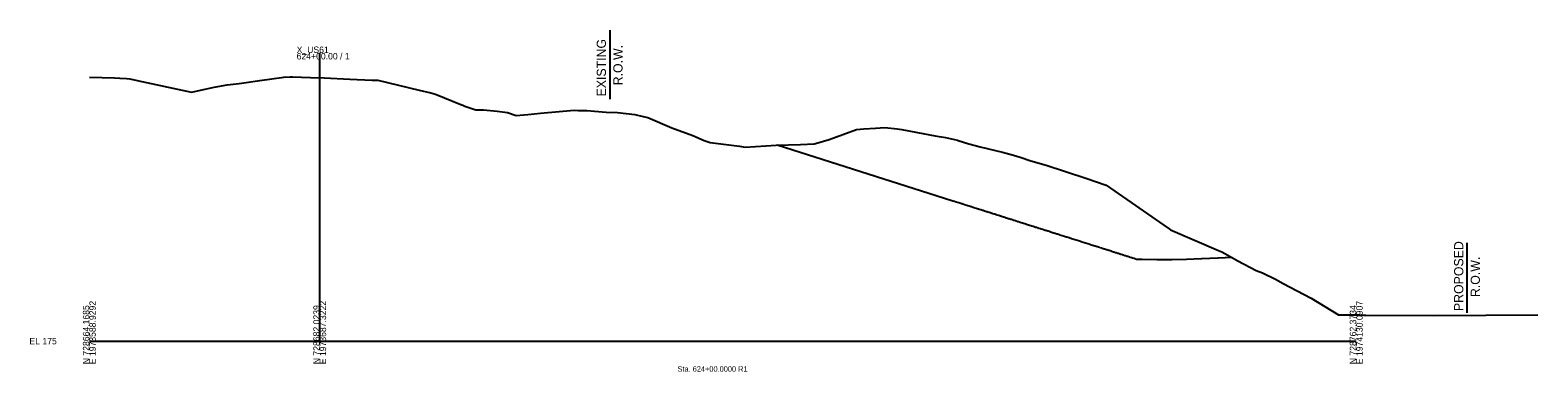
# Model space of a CAD drawing. Extents: x -26 to 1629, y -25 to 9635.
# Drawn here: x 974 to 1629, y -13 to 135 of the extents above; entities that cross this region are included whole.
import ezdxf

# ---------------------------------------------------------------- set-up
doc = ezdxf.new("R2010")
doc.units = 0
for name, color, linetype in [('Draft_XS_Grid', 7, 'Continuous'), ('Draft_XS_Text', 7, 'Continuous'), ('DTM_X_GROUND', 7, 'Continuous'), ('XS_CELL', 7, 'Continuous'), ('XS_P_GROUND', 7, 'Continuous'), ('XS_P_ROW', 7, 'Continuous'), ('XS_X_ROW', 7, 'Continuous')]:
    doc.layers.add(name, color=color, linetype=linetype)

msp = doc.modelspace()

# ---------------------------------------------------------------- linework, layer by layer
at = {"layer": 'DTM_X_GROUND'}
msp.add_lwpolyline([(1000, 114.48), (1010.96, 114.2), (1013.31, 114.15), (1016.1, 113.91), (1017.53, 113.79), (1020.8, 113.08), (1044.32, 108.06), (1050.31, 109.32), (1054.16, 110.13), (1059.81, 111.19), (1065.07, 111.81), (1074.07, 113.05), (1084.46, 114.48), (1087.2, 114.59), (1088.13, 114.63), (1096.02, 114.37), (1102, 114.17), (1113.06, 113.68), (1122.74, 113.25), (1123.28, 113.24), (1125.23, 113.19), (1143.22, 108.82), (1148.23, 107.66), (1150.24, 107.15), (1161.3, 102.65), (1162.21, 102.3), (1163.05, 101.98), (1167.75, 100.3), (1171.13, 100.4), (1177.05, 99.82), (1181.48, 99.14), (1185.25, 97.91), (1188.63, 98.18), (1190.36, 98.32), (1195.82, 98.85), (1210.42, 100.18), (1212.18, 100.12), (1215.92, 100.01), (1224.35, 99.34), (1229.31, 99.18), (1236.83, 98.34), (1240.5, 97.48), (1242.4, 97.03), (1252.93, 92.49), (1261.95, 89.24), (1266.97, 87.11), (1269.53, 86.23), (1282.23, 84.55), (1284.75, 84.21), (1298.13, 84.97), (1308.68, 85.33), (1314.62, 85.55), (1316.28, 86.04), (1321.16, 87.49), (1333.03, 91.83), (1336.21, 92.06), (1341.37, 92.44), (1345.38, 92.75), (1350.7, 92.06), (1352.78, 91.8), (1359.57, 90.51), (1367.19, 89.01), (1371.71, 88.42), (1376.94, 87.13), (1377.24, 87.03), (1381.86, 85.59), (1386.79, 84.35), (1396.4, 82.02), (1401.21, 80.65), (1404.1, 79.78), (1408.75, 78.22), (1415.35, 76.37), (1432.61, 70.7), (1441.38, 67.61), (1450.42, 61.4), (1466.46, 50.38), (1468.82, 48.68), (1469.36, 48.34), (1490.18, 39.4), (1491.62, 38.83), (1492.92, 38.1), (1498.61, 34.91), (1506.62, 30.61), (1509.37, 29.71), (1514.9, 26.94), (1518.23, 25.05), (1530.49, 18.61), (1542.25, 11.42), (1545.81, 11.41), (1550.25, 11.39), (1551.07, 11.38), (1553.13, 11.32), (1554.11, 11.32), (1583.63, 11.21), (1628.84, 11.48)], dxfattribs=at)
at = {"layer": 'XS_CELL'}
for p, q in [((1100, 0), (1100, 125)), ((1000, 0), (1100, 0)), ((1100, 0), (1550, 0))]:
    msp.add_line(p, q, dxfattribs=at)
at = {"layer": 'XS_P_GROUND'}
msp.add_lwpolyline([(1496.13, 36.36), (1490, 35.99), (1489.9, 35.99), (1483.03, 35.67), (1482.83, 35.67), (1476.34, 35.46), (1470.11, 35.35), (1469.83, 35.34), (1463.63, 35.32), (1463.39, 35.32), (1457.12, 35.4), (1456.92, 35.4), (1454.74, 35.47), (1454.65, 35.48), (1453.91, 35.71), (1453.64, 35.8), (1452.89, 36.04), (1452.63, 36.12), (1451.87, 36.36), (1451.62, 36.44), (1450.86, 36.68), (1450.61, 36.76), (1449.84, 37), (1449.6, 37.08), (1448.82, 37.33), (1448.59, 37.4), (1447.8, 37.65), (1447.58, 37.72), (1447.39, 37.78), (1447.33, 37.8), (1446.73, 37.99), (1446.57, 38.04), (1446.47, 38.07), (1446.44, 38.08), (1445.74, 38.3), (1445.56, 38.36), (1444.75, 38.62), (1444.55, 38.68), (1443.73, 38.94), (1443.54, 39), (1442.71, 39.27), (1442.53, 39.32), (1441.69, 39.59), (1441.52, 39.64), (1440.68, 39.91), (1440.51, 39.96), (1439.66, 40.23), (1439.5, 40.28), (1438.64, 40.56), (1438.49, 40.6), (1437.62, 40.88), (1437.48, 40.92), (1436.6, 41.2), (1436.47, 41.24), (1435.58, 41.53), (1435.46, 41.57), (1434.56, 41.85), (1434.45, 41.89), (1433.54, 42.18), (1433.44, 42.21), (1432.52, 42.5), (1432.43, 42.53), (1431.5, 42.82), (1431.42, 42.85), (1430.48, 43.15), (1430.41, 43.17), (1429.46, 43.47), (1429.4, 43.49), (1428.44, 43.79), (1428.39, 43.81), (1427.42, 44.12), (1427.38, 44.13), (1426.4, 44.44), (1426.37, 44.45), (1425.38, 44.77), (1425.36, 44.77), (1424.36, 45.09), (1424.35, 45.09), (1424.06, 45.18), (1423.34, 45.41), (1423.32, 45.42), (1422.33, 45.73), (1422.29, 45.75), (1421.32, 46.05), (1421.25, 46.08), (1420.31, 46.37), (1420.3, 46.38), (1420.18, 46.41), (1420.09, 46.44), (1419.3, 46.69), (1419.17, 46.73), (1418.29, 47.01), (1418.13, 47.06), (1417.28, 47.33), (1417.09, 47.39), (1416.27, 47.65), (1416.05, 47.73), (1415.26, 47.98), (1415.01, 48.06), (1414.25, 48.3), (1413.96, 48.39), (1413.24, 48.62), (1412.92, 48.72), (1412.23, 48.94), (1411.87, 49.05), (1411.22, 49.26), (1410.82, 49.38), (1410.21, 49.58), (1409.78, 49.72), (1409.2, 49.9), (1408.73, 50.05), (1408.19, 50.22), (1407.67, 50.38), (1407.18, 50.54), (1406.62, 50.72), (1406.17, 50.86), (1405.57, 51.05), (1405.16, 51.18), (1404.51, 51.39), (1404.15, 51.5), (1403.45, 51.72), (1403.14, 51.82), (1402.39, 52.06), (1402.13, 52.14), (1401.33, 52.4), (1401.12, 52.46), (1400.27, 52.73), (1400.11, 52.78), (1399.2, 53.07), (1399.1, 53.1), (1398.13, 53.41), (1398.09, 53.42), (1397.44, 53.63), (1397.08, 53.74), (1396.8, 53.83), (1396.07, 54.06), (1395.99, 54.09), (1395.97, 54.1), (1395.81, 54.15), (1395.31, 54.31), (1395.12, 54.37), (1395.06, 54.39), (1394.77, 54.48), (1394.05, 54.71), (1393.96, 54.74), (1393.93, 54.74), (1393.71, 54.81), (1393.04, 55.03), (1392.97, 55.05), (1392.77, 55.11), (1392.22, 55.29), (1392.03, 55.35), (1391.83, 55.41), (1391.16, 55.62), (1391.05, 55.66), (1391.02, 55.67), (1390.65, 55.78), (1390.01, 55.99), (1389.84, 56.04), (1389.72, 56.08), (1389.43, 56.17), (1389, 56.31), (1388.58, 56.44), (1387.99, 56.63), (1387.71, 56.72), (1386.98, 56.95), (1386.36, 57.15), (1385.97, 57.27), (1385.9, 57.29), (1384.96, 57.59), (1383.98, 57.9), (1383.95, 57.91), (1382.99, 58.22), (1382.94, 58.23), (1382.86, 58.26), (1381.93, 58.55), (1381.43, 58.71), (1380.92, 58.87), (1380.9, 58.88), (1379.91, 59.19), (1379.25, 59.4), (1378.9, 59.51), (1378.68, 59.58), (1377.89, 59.83), (1377.52, 59.95), (1376.88, 60.15), (1376.32, 60.33), (1375.87, 60.47), (1375.71, 60.53), (1374.86, 60.8), (1374.45, 60.92), (1298.62, 84.98)], dxfattribs=at)
at = {"layer": 'XS_P_ROW'}
msp.add_line((1598, 42.67), (1598, 12.35), dxfattribs=at)
at = {"layer": 'XS_X_ROW'}
msp.add_line((1226, 134.9), (1226, 105), dxfattribs=at)

# ---------------------------------------------------------------- texts
at = {"layer": 'Draft_XS_Grid'}
msp.add_text('-', height=0.0001, dxfattribs=at).set_placement((1000, 0))
at = {"layer": 'Draft_XS_Text'}
msp.add_text('Sta. 624+00.0000 R1', height=2.4, dxfattribs=at).set_placement((1255.34, -13.25))
at = {"layer": 'XS_CELL'}
for s, p in [('X_US61', (1090, 125)), ('624+00.00 / 1', (1090, 122.2)), ('EL 175', (974, -1.4))]:
    msp.add_text(s, height=2.8, dxfattribs=at).set_placement(p)
for s, p in [('N 728664.1685', (1000, -10)), ('E 1973588.9292', (1002.8, -10)), ('N 728682.0239', (1100, -10)), ('E 1973687.3222', (1102.8, -10)), ('N 728762.3734', (1550, -10)), ('E 1974130.0907', (1552.8, -10))]:
    msp.add_text(s, height=2.8, rotation=90, dxfattribs=at).set_placement(p)
at = {"layer": 'XS_P_ROW'}
for s, p in [('PROPOSED', (1596.48, 13.06)), ('R.O.W.', (1603.68, 19.13))]:
    msp.add_text(s, height=4, rotation=90, dxfattribs=at).set_placement(p)
at = {"layer": 'XS_X_ROW'}
for s, p in [('EXISTING', (1224.28, 106.14)), ('R.O.W.', (1231.48, 110.98))]:
    msp.add_text(s, height=4, rotation=90, dxfattribs=at).set_placement(p)

doc.saveas('drawing.dxf')
